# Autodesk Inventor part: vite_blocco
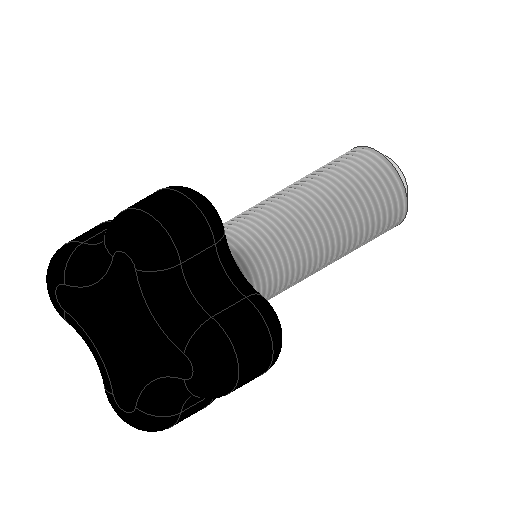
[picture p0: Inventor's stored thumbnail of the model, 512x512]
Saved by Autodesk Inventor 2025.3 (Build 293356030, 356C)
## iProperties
Created: 2025-09
Part Number: vite_blocco
Material: Generico
Document SubType Name: Modeling
Designer: Ryzen5700u
Density: 1 g/cm^3
Appearance: Default
Author: Ryzen5700u
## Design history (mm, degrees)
sketch "Schizzo1"
  geometry: C1 r 2.75 at (22, -2.5) reference; 1 further point
extrude "Estrusione1" new body sketch "Schizzo1" distance "d0" = 16; taper "d1" = 0 deg
sketch "Schizzo2"
  geometry: C1 r 8 at (0, 0); 1 further point
  constraints: 1 centre point
  dimensions: "d2" = 16 diameter of C1
extrude "Estrusione2" join sketch "Schizzo2" distance "d3" = 7; taper "d4" = 0 deg
chamfer "Smusso2" distance "d8" = 1; stored, may be unused: second distance "d9" = 2, angle "d10" = 45 deg
feature "Filettatura1" dims "d11" = 14, "d12" = 0
sketch "Schizzo3" dims "d13" = 6
  geometry: L1 (0, 0)-(0, 8) reference; L2 (0, 0)-(8, 0) reference; C1 r 3 at (5, 0); C2 r 3.5 at (6.357, 6.357); A1 r 8 centre (0, 0) between (0, 8) and (8, 0) reference; 5 further points
  constraints: 4 end point, 2 centre point, 2 point on circle, 2 point on line, 2 tangent, 2 vertical, 1 horizontal, 1 perpendicular, 4 other
  dimensions: "d14" = 6 diameter of C1; "d15" = 7 diameter of C2
extrude "Estrusione3" cut sketch "Schizzo3" extent not by distance; stored distance "d16" = 0; taper "d17" = 0 deg
pattern_circular "Serie circolare1" dims angle "d19" = 360 deg
fillet "Raccordo1" dims "d21" = 2
node "Solido1"
node "Riferimento1"
